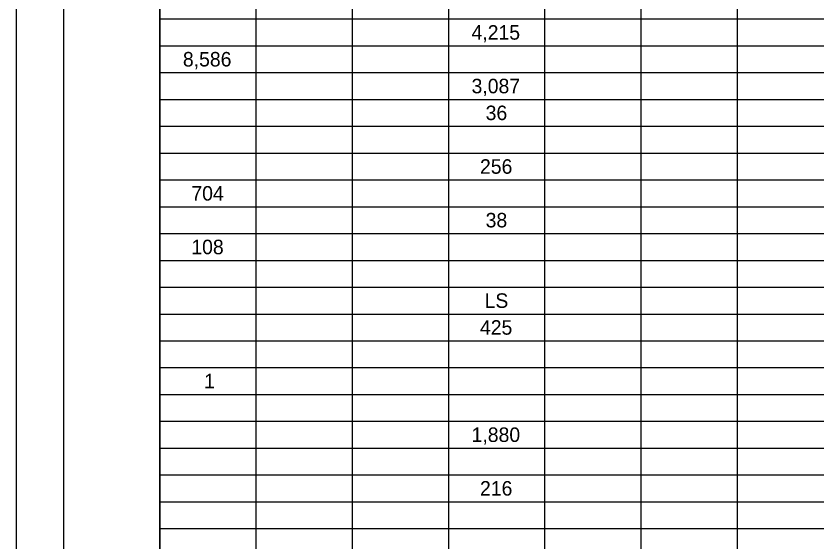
# Model space of a CAD drawing. Extents: x 0 to 34, y 0 to 22.
# Drawn here: x 0 to 8.36, y 11 to 16.49 of the extents above; entities that cross this region are included whole.
import ezdxf

# ---------------------------------------------------------------- set-up
doc = ezdxf.new("R2010")
doc.units = 0
for name, color, linetype in [('SH_Border', 7, 'Continuous'), ('SH_Cut_Line', 7, 'Continuous'), ('SH_Text', 7, 'Continuous')]:
    doc.layers.add(name, color=color, linetype=linetype)

msp = doc.modelspace()

# ---------------------------------------------------------------- linework, layer by layer
at = {"layer": 'SH_Border'}
for points in [[(0.5, 21.5), (1.5, 21.5), (1.5, 0.5), (0.5, 0.5)], [(1.5, 21.5), (33.5, 21.5), (33.5, 0.5), (1.5, 0.5)]]:
    msp.add_lwpolyline(points, close=True, dxfattribs=at)
at = {"layer": 'SH_Cut_Line'}
msp.add_lwpolyline([(0, 0), (34, 0), (34, 22), (0, 22)], close=True, dxfattribs=at)
at = {"layer": 'SH_Text'}
for p, q in [((1.5, 21.5), (1.5, 0.5)), ((2.5047, 20.94), (2.5047, 0.5)), ((3.5094, 20.94), (3.5094, 0.5)), ((4.5141, 20.94), (4.5141, 0.5)), ((5.5188, 20.94), (5.5188, 0.5)), ((6.5235, 20.94), (6.5235, 0.5)), ((7.5282, 20.94), (7.5282, 0.5)), ((1.5, 16.46), (32.0035, 16.46)), ((1.5, 16.18), (32.0035, 16.18)), ((1.5, 15.9), (32.0035, 15.9)), ((1.5, 15.62), (32.0035, 15.62)), ((1.5, 15.34), (32.0035, 15.34)), ((1.5, 15.06), (32.0035, 15.06)), ((1.5, 14.78), (32.0035, 14.78)), ((1.5, 14.5), (32.0035, 14.5)), ((1.5, 14.22), (32.0035, 14.22)), ((1.5, 13.94), (32.0035, 13.94)), ((1.5, 13.66), (32.0035, 13.66)), ((1.5, 13.38), (32.0035, 13.38)), ((1.5, 13.1), (32.0035, 13.1)), ((1.5, 12.82), (32.0035, 12.82)), ((1.5, 12.54), (32.0035, 12.54)), ((1.5, 12.26), (32.0035, 12.26)), ((1.5, 11.98), (32.0035, 11.98)), ((1.5, 11.7), (32.0035, 11.7)), ((1.5, 11.42), (32.0035, 11.42)), ((1.5, 11.14), (32.0035, 11.14))]:
    msp.add_line(p, q, dxfattribs=at)

# ---------------------------------------------------------------- texts
for s, height, p in [('4,215', 0.15153, (4.7559, 16.2442)), ('8,586', 0.15153, (1.7424, 15.9642)), ('3,087', 0.15153, (4.7565, 15.6842)), ('36', 0.15153, (4.9036, 15.4042)), ('256', 0.15153, (4.8447, 14.8442)), ('704', 0.15153, (1.831, 14.5642)), ('38', 0.15153, (4.9035, 14.2842)), ('108', 0.15153, (1.8305, 14.0042)), ('LS', 0.15153, (4.8925, 13.4442)), ('425', 0.15153, (4.8442, 13.1642)), ('1', 0.1515, (1.963, 12.6042)), ('1,880', 0.15153, (4.7568, 12.0442)), ('216', 0.15153, (4.8447, 11.4842))]:
    msp.add_text(s, height=height, dxfattribs=at).set_placement(p)

doc.saveas('drawing.dxf')
